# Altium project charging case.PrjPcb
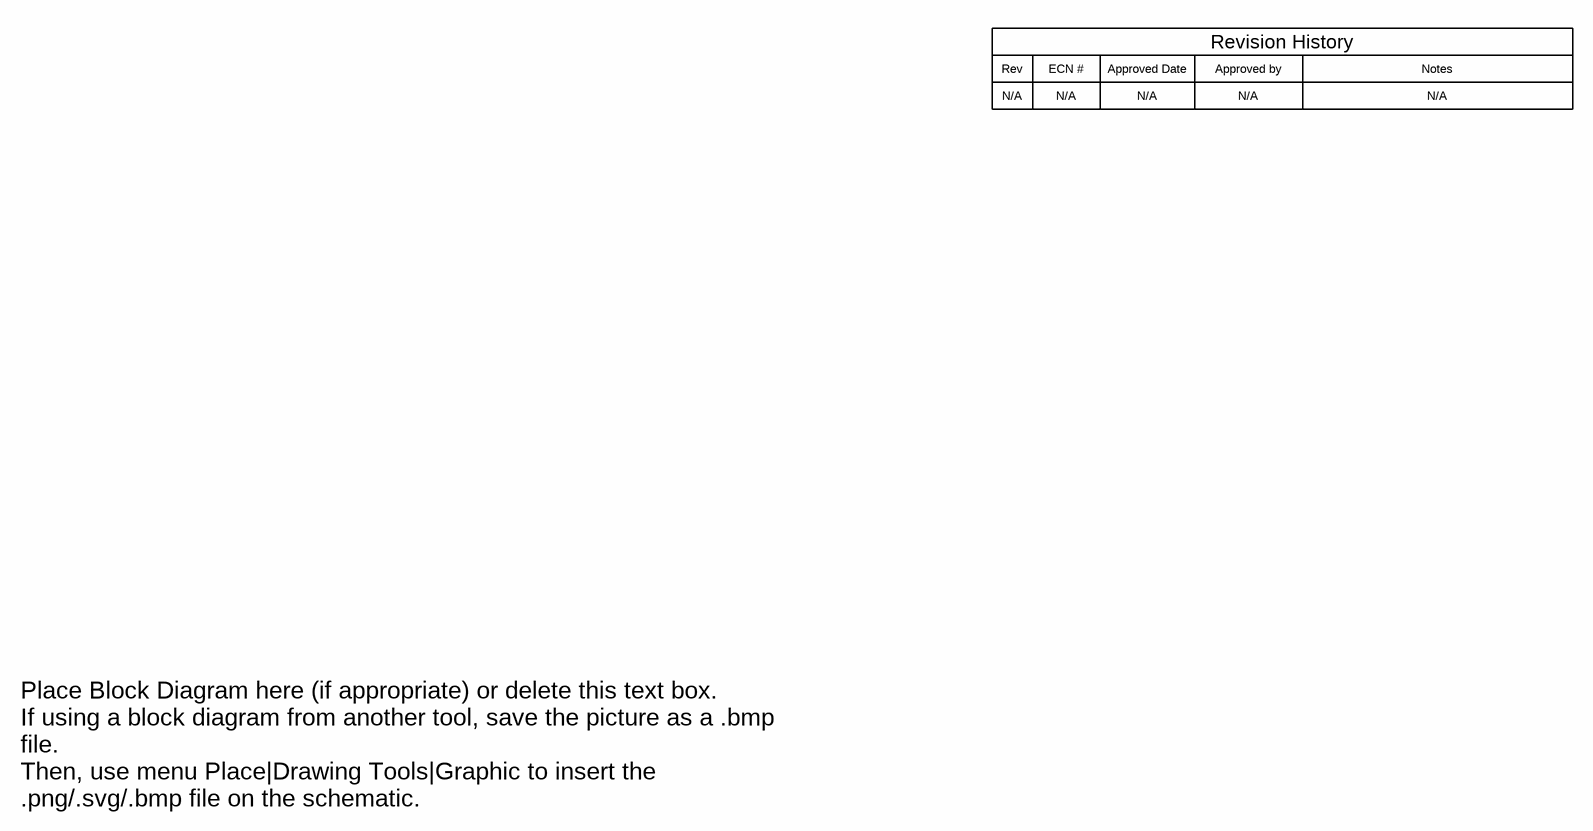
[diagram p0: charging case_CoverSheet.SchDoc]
CopyrightYear: 2017; PCB_Layout: Who did the Layout?; PCB_Rev: E1; PRJ_Customer: Public Release; PRJ_Engineer: Enter name of project lead; PRJ_Number: XX####; PRJ_Title: Change in menu Project|Project Options|Parameters; SCH_Rev: E1; TechSupport: http://www.ti.com/support; TID: N/A
3 sheets, 81 parts. Net scope: global (net labels, ports and power ports of the same name join across sheets).
Board file: charging case_PCB.PcbDoc
Sheets:
  charging case_CoverSheet.SchDoc
  charging case_BlankSheet.SchDoc
  charging case_EVM_Hardware.SchDoc

## Sheet charging case_CoverSheet.SchDoc
size 431 x 279 mm; Date: Not shown in title block; ApprovedBy: Not shown in title block; CheckedBy: Not shown in title block; Author: Not shown in title block; CompanyName: Not shown in title block; Engineer: Not shown in title block; Organization: Not shown in title block; Address1: Not shown in title block; Address2: Not shown in title block; Address3: Not shown in title block; Address4: Not shown in title block; DocumentNumber: 1; Revision: Use project parameter SCH_Rev; SheetNumber: 1; SheetTotal: 3; PageSetup: Record=PageOptions¦CenterHorizontal=True¦CenterVertical=True¦PrintScale=1.00¦XCorrection=1.00¦YCorrection=1.00¦PrintKind=0¦BorderSize=5000000¦LeftOffset=0¦BottomOffset=0¦Orientation=2¦PaperLength=1000¦PaperWidth=1000¦Scale=100¦PaperSource=15¦PrintQuality=600¦MediaType=1¦DitherType=10¦PaperKind=Letter¦PrintScaleMode=1

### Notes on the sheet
- Rev
- N/A
- ECN #
- Approved Date
- Approved by
- Revision History
- Notes
- Place Block Diagram here (if appropriate) or delete this text box.
  If using a block diagram from another tool, save the picture as a .bmp file.
  Then, use menu Place|Drawing Tools|Graphic to insert the .png/.svg/.bmp file on the schematic.

## Sheet charging case_BlankSheet.SchDoc
size 431 x 279 mm; Date: Not shown in title block; ApprovedBy: Not shown in title block; CheckedBy: Not shown in title block; Author: Not shown in title block; CompanyName: Not shown in title block; Engineer: Not shown in title block; Organization: Not shown in title block; Address1: Not shown in title block; Address2: Not shown in title block; Address3: Not shown in title block; Address4: Not shown in title block; DocumentNumber: 1; Revision: Use project parameter SCH_Rev; SheetNumber: 2; SheetTotal: 3; PageSetup: Record=PageOptions¦CenterHorizontal=True¦CenterVertical=True¦PrintScale=1.00¦XCorrection=1.00¦YCorrection=1.00¦PrintKind=0¦BorderSize=5000000¦LeftOffset=0¦BottomOffset=0¦Orientation=2¦PaperLength=1000¦PaperWidth=1000¦Scale=100¦PaperSource=15¦PrintQuality=600¦MediaType=1¦DitherType=10¦PaperKind=Letter¦PrintScaleMode=1
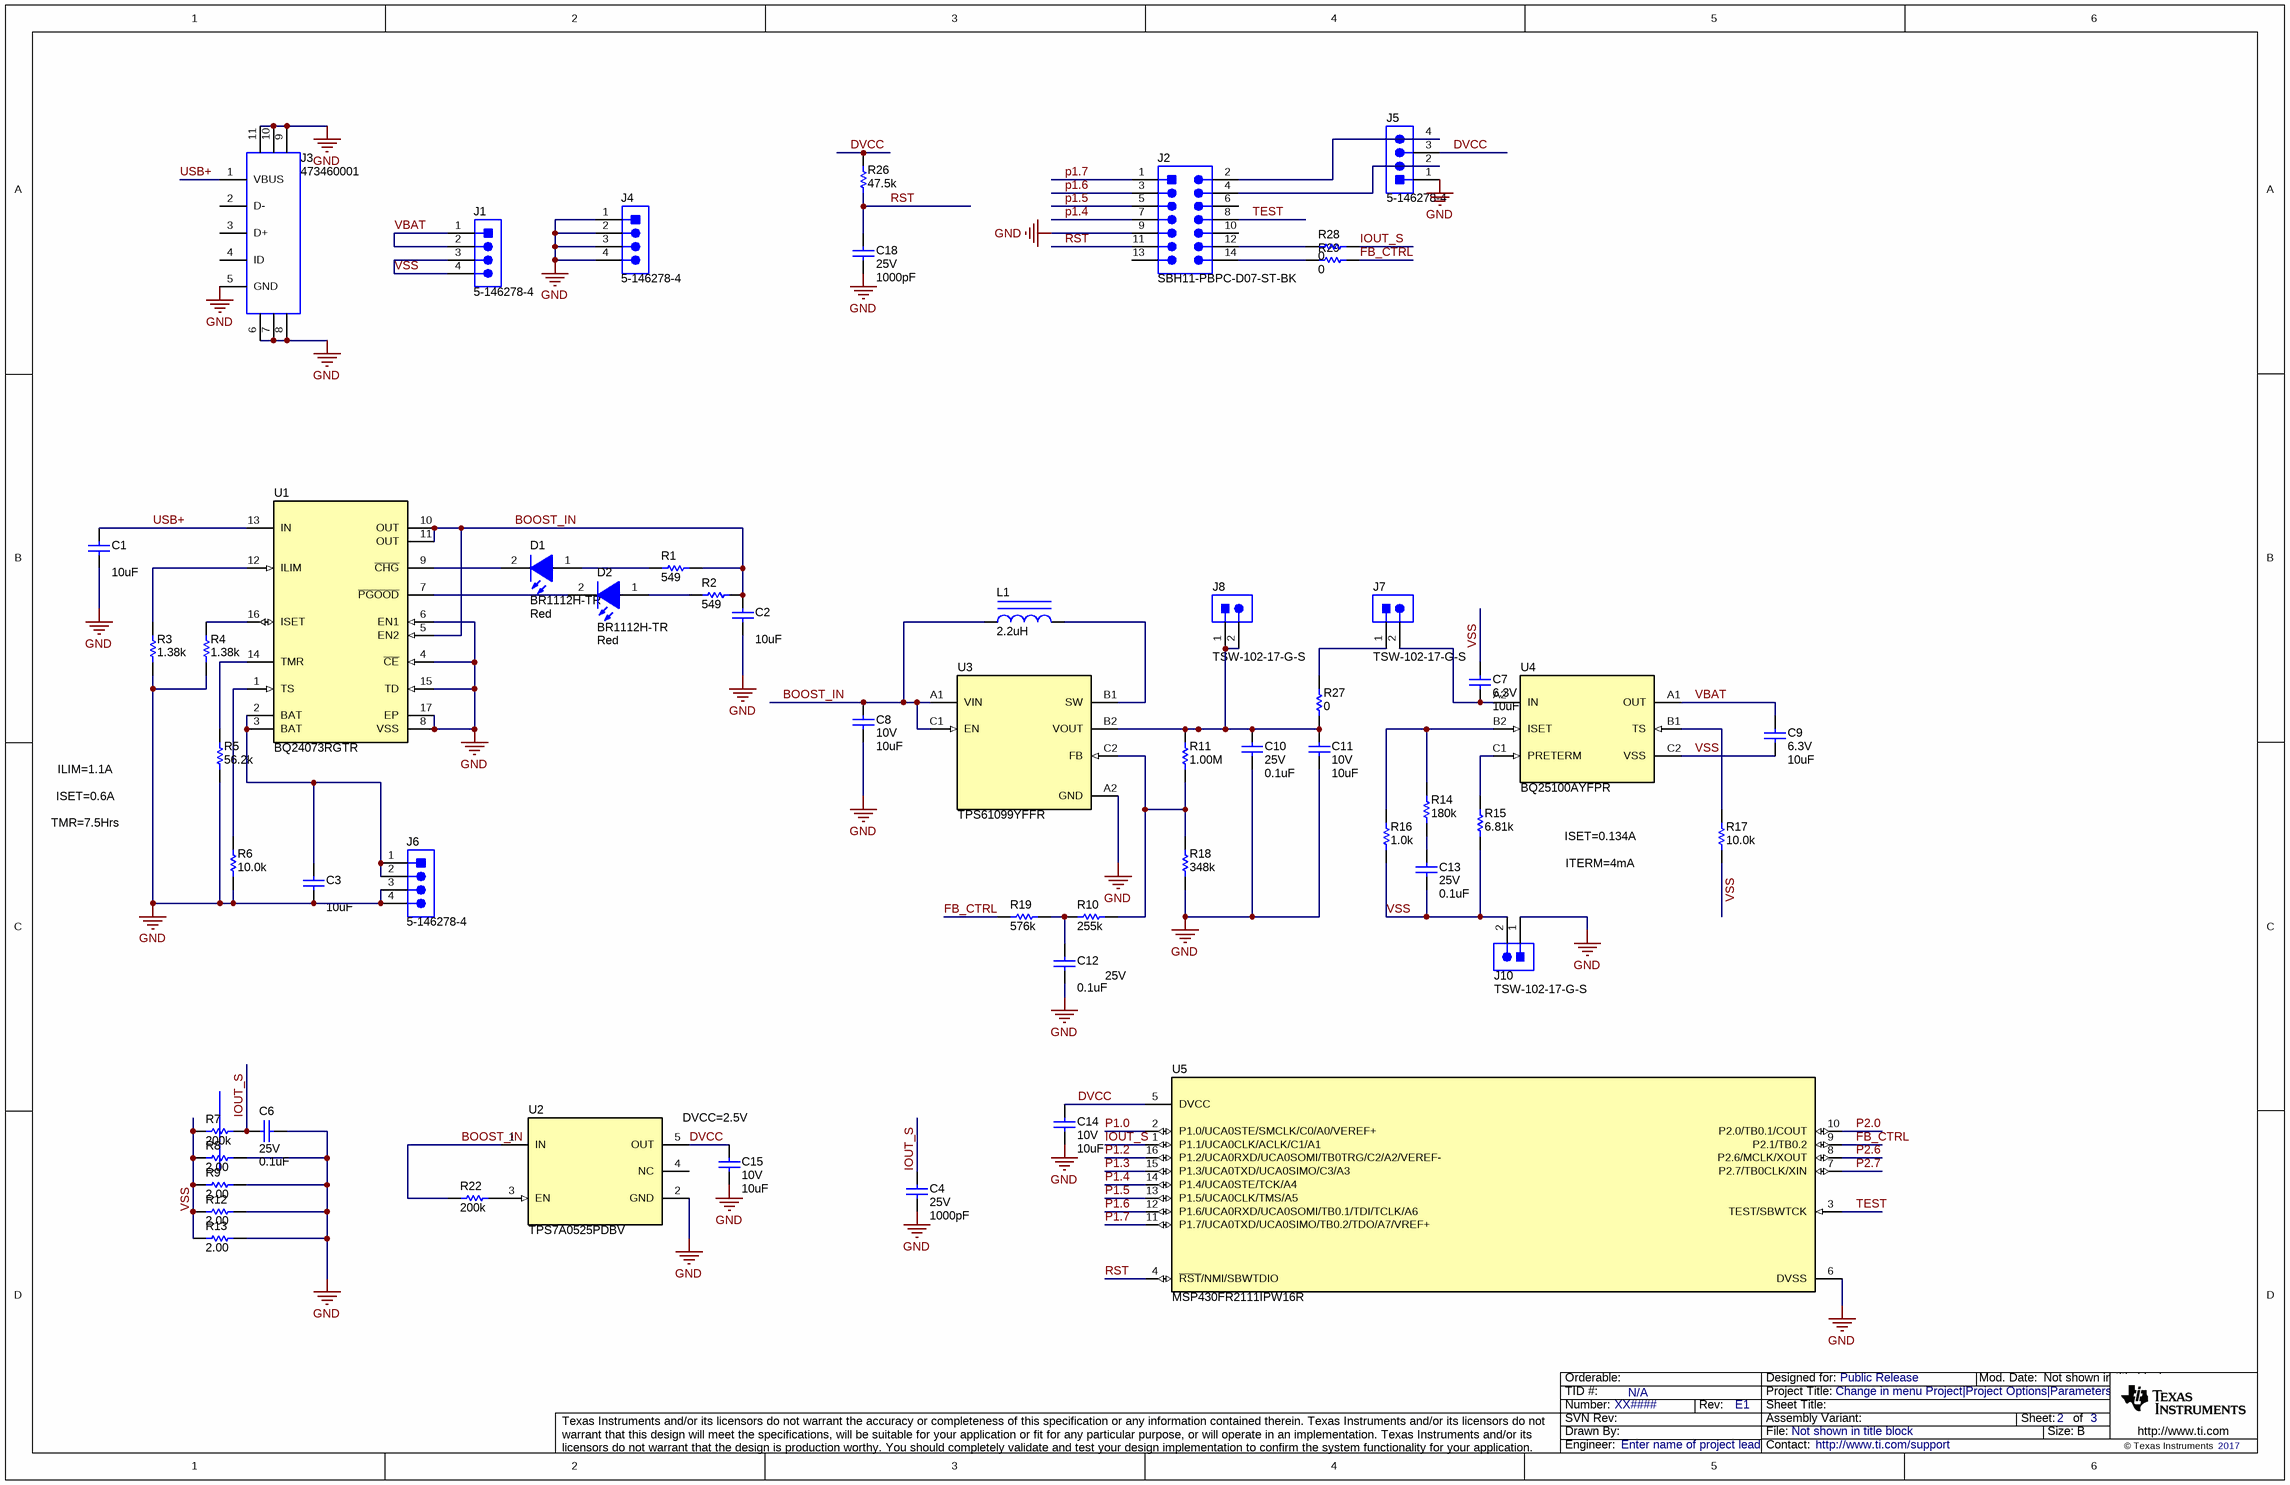
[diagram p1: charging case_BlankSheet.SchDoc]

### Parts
C1  ValueDisplayed: 10uF  [0603]  (hidden comment: GRM188Z71A106MA73D)
C2  ValueDisplayed: 10uF  [0603]  (hidden comment: GRM188Z71A106MA73D)
C3  ValueDisplayed: 10uF  [0603]  (hidden comment: GRM188Z71A106MA73D)
C4  VDC_V: 25V  ValueDisplayed: 1000pF  [0603]  (hidden comment: GRM1885C1E102JA01D)
C6  VDC_V: 25V  ValueDisplayed: 0.1uF  [0603]  (hidden comment: 06033D104KAT2A)
C7  VDC_V: 6.3V  ValueDisplayed: 10uF  [0402_070]  (hidden comment: C1005X5R0J106M050BC)
C8  VDC_V: 10V  ValueDisplayed: 10uF  [0603]  (hidden comment: GRM188Z71A106MA73D)
C9  VDC_V: 6.3V  ValueDisplayed: 10uF  [0402_070]  (hidden comment: C1005X5R0J106M050BC)
C10  VDC_V: 25V  ValueDisplayed: 0.1uF  [0603]  (hidden comment: 06033D104KAT2A)
C11  VDC_V: 10V  ValueDisplayed: 10uF  [0603]  (hidden comment: GRM188Z71A106MA73D)
C12  VDC_V: 25V  ValueDisplayed: 0.1uF  [0603]  (hidden comment: 06033D104KAT2A)
C13  VDC_V: 25V  ValueDisplayed: 0.1uF  [0402]  (hidden comment: GRM155R61E104KA87D)
C14  VDC_V: 10V  ValueDisplayed: 10uF  [0603]  (hidden comment: GRM188Z71A106MA73D)
C15  VDC_V: 10V  ValueDisplayed: 10uF  [0603]  (hidden comment: GRM188Z71A106MA73D)
C18  VDC_V: 25V  ValueDisplayed: 1000pF  [0603]  (hidden comment: GRM1885C1E102JA01D)
D1  BR1112H-TR  value Red  [BR1112H_Red]
D2  BR1112H-TR  value Red  [BR1112H_Red]
J1  5-146278-4  [TE_5-146278-4]
J2  SBH11-PBPC-D07-ST-BK  [CONN_SBH11-PBPC-D07-ST-BK]
J3  473460001  [CONN_47346-0001]
J4  5-146278-4  [TE_5-146278-4]
J5  5-146278-4  [TE_5-146278-4]
J6  5-146278-4  [TE_5-146278-4]
J7  TSW-102-17-G-S  [Samtec_TSW-102-17-x-S]
J8  TSW-102-17-G-S  [Samtec_TSW-102-17-x-S]
J10  TSW-102-17-G-S  [Samtec_TSW-102-17-x-S]
L1  ValueDisplayed: 2.2uH  [DFE252012C]  (hidden comment: DFE252012F-2R2M=P2)
R1  ValueDisplayed: 549  [0603]  (hidden comment: RT0603DRE07549RL)
R2  ValueDisplayed: 549  [0603]  (hidden comment: RT0603DRE07549RL)
R3  ValueDisplayed: 1.38k  [0603]  (hidden comment: RT0603DRE071K38L)
R4  ValueDisplayed: 1.38k  [0603]  (hidden comment: RT0603DRE071K38L)
R5  ValueDisplayed: 56.2k  [0603]  (hidden comment: RC0603FR-0756K2L)
R6  ValueDisplayed: 10.0k  [0603]  (hidden comment: RC0603FR-0710KL)
R7  ValueDisplayed: 200k  [0603]  (hidden comment: RG1608P-204-B-T5)
R8  ValueDisplayed: 2.00  [0603]  (hidden comment: RC0603FR-072RL)
R9  ValueDisplayed: 2.00  [0603]  (hidden comment: RC0603FR-072RL)
R10  ValueDisplayed: 255k  [0603]  (hidden comment: RT0603DRE07255KL)
R11  ValueDisplayed: 1.00M  [0603]  (hidden comment: MCT06030C1004FP500)
R12  ValueDisplayed: 2.00  [0603]  (hidden comment: RC0603FR-072RL)
R13  ValueDisplayed: 2.00  [0603]  (hidden comment: RC0603FR-072RL)
R14  ValueDisplayed: 180k  [0402]  (hidden comment: RC0402FR-07180KL)
R15  ValueDisplayed: 6.81k  [0402]  (hidden comment: RC0402FR-076K81L)
R16  ValueDisplayed: 1.0k  [0603]  (hidden comment: RC0603JR-071KL)
R17  ValueDisplayed: 10.0k  [0402]  (hidden comment: RC0402FR-0710KL)
R18  ValueDisplayed: 348k  [0603]  (hidden comment: RT0603DRE07348KL)
R19  ValueDisplayed: 576k  [0603]  (hidden comment: RC0603FR-07576KL)
R22  ValueDisplayed: 200k  [0603]  (hidden comment: RG1608P-204-B-T5)
R26  ValueDisplayed: 47.5k  [0603]  (hidden comment: RT0603BRD0747K5L)
R27  ValueDisplayed: 0  [0603]  (hidden comment: RMCF0603ZT0R00)
R28  ValueDisplayed: 0  [0603]  (hidden comment: RMCF0603ZT0R00)
R29  ValueDisplayed: 0  [0603]  (hidden comment: RMCF0603ZT0R00)
U1  PartNumber: BQ24073RGTR  [RGT0016C]  (hidden comment: BQ24230RGTR)
U2  PartNumber: TPS7A0525PDBV  [DBV0005A_N]  (hidden comment: TPS7A0533PDBV)
U3  TPS61099YFFR  [YFF0006AFAD]
U4  BQ25100AYFPR  [YFP0006AFAV]
U5  MSP430FR2111IPW16R  [PW0016A_L]

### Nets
GND: C1.2 C2.2 C3.2 C4.2 C6.1 C8.2 C10.2 C11.2 C12.2 C14.2 C15.2 C18.2 J2.9 J3.5(GND) J3.6 J3.7 J3.8 J3.9 J3.10 J3.11 J4.1 J4.2 J4.3 J4.4 J5.1 J6.3 J6.4 J10.1 R3.1 R4.1 R5.1 R6.1 R8.2 R9.2 R12.2 R13.2 R18.1 U1.4(~{CE}) U1.6(EN1) U1.8(VSS) U1.15(TD) U1.17(EP) U2.2(GND) U3.A2(GND) U5.6(DVSS)
BOOST_IN: C2.1 C8.1 L1.1 R1.1 R2.1 R22.2 U1.5(EN2) U1.10(OUT) U1.11(OUT) U2.1(IN) U3.A1(VIN) U3.C1(EN)
DVCC: C14.1 C15.1 J5.3 R26.2 U2.5(OUT) U5.5(DVCC)
FB_CTRL: R19.1 R29.1 U5.9(P2.1/TB0.2)
IOUT_S: C4.1 C6.2 R7.1 R28.1 U5.1(P1.1/UCA0CLK/ACLK/C1/A1)
P1.0: U5.2(P1.0/UCA0STE/SMCLK/C0/A0/VEREF+)
P1.2: U5.16(P1.2/UCA0RXD/UCA0SOMI/TB0TRG/C2/A2/VEREF-)
P1.3: U5.15(P1.3/UCA0TXD/UCA0SIMO/C3/A3)
P1.4: J2.7 U5.14(P1.4/UCA0STE/TCK/A4)
P1.5: J2.5 U5.13(P1.5/UCA0CLK/TMS/A5)
P1.6: J2.3 U5.12(P1.6/UCA0RXD/UCA0SOMI/TB0.1/TDI/TCLK/A6)
P1.7: J2.1 U5.11(P1.7/UCA0TXD/UCA0SIMO/TB0.2/TDO/A7/VREF+)
P2.0: U5.10(P2.0/TB0.1/COUT)
P2.6: U5.8(P2.6/MCLK/XOUT)
P2.7: U5.7(P2.7/TB0CLK/XIN)
RST: C18.1 J2.11 R26.1 U5.4(~{RST}/NMI/SBWTDIO)
TEST: J2.8 U5.3(TEST/SBWTCK)
USB+: C1.1 J3.1(VBUS) U1.13(IN)
VBAT: C9.1 J1.1 J1.2 U4.A1(OUT)
VSS: C7.1 C9.2 C13.2 J1.3 J1.4 J10.2 R7.2 R8.1 R9.1 R12.1 R13.1 R15.1 R16.1 R17.1 U4.C2(VSS)
NetC3_1: C3.1 J6.1 J6.2 U1.2(BAT) U1.3(BAT)
NetC7_2: C7.2 J7.2 U4.A2(IN)
NetC10_1: C10.1 C11.1 J8.1 J8.2 R11.2 R27.1 U3.B2(VOUT)
NetC12_1: C12.1 R10.1 R19.2
NetC13_1: C13.1 R14.1
NetD1_1: D1.1(A) R1.2
NetD1_2: D1.2(K) U1.9(~{CHG})
NetD2_1: D2.1(A) R2.2
NetD2_2: D2.2(K) U1.7(~{PGOOD})
NetJ2_2: J2.2 J5.4
NetJ2_4: J2.4 J5.2
NetJ2_12: J2.12 R28.2
NetJ2_14: J2.14 R29.2
NetJ7_1: J7.1 R27.2
NetL1_2: L1.2 U3.B1(SW)
NetR3_2: R3.2 U1.12(ILIM)
NetR4_2: R4.2 U1.16(ISET)
NetR5_2: R5.2 U1.14(TMR)
NetR6_2: R6.2 U1.1(TS)
NetR10_2: R10.2 R11.1 R18.2 U3.C2(FB)
NetR14_2: R14.2 R16.2 U4.B2(ISET)
NetR15_2: R15.2 U4.C1(PRETERM)
NetR17_2: R17.2 U4.B1(TS)
NetR22_1: R22.1 U2.3(EN)

Not connected (* = marked no-connect by the designer): J2 6 10 13; J3 2(D-) 3(D+) 4(ID); U2 4(NC)

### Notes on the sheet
- ILIM=1.1A
- ISET=0.6A
- TMR=7.5Hrs
- ISET=0.134A
- ITERM=4mA
- DVCC=2.5V

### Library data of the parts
C1 = CMP-0007497-5: CAP, CERM, 10 uF, 10 V, +/- 20%, X7R, 0603; Manufacturer: MuRata; TaMin_C: -55°C; Polarized: N; SizeAreaWB_mm2: 4.68; Value1: Unknown; U/M: EA; Value: 10uF; TaMax_C: 125°C; SizeZ_mm: 1; SizeX_mm: 1.6; SizeY_mm: 0.8; Value2: 10V; SizeArea_mm2: 1.28; Cap_F: 10µF; AEC Category: Q200
C2 C3 = CMP-0007497-5: CAP, CERM, 10 uF, 10 V, +/- 20%, X7R, 0603; Manufacturer: MuRata; TaMin_C: -55°C; Polarized: N; SizeAreaWB_mm2: 4.68; Value1: Unknown; U/M: EA; Value: 10uF; TaMax_C: 125°C; SizeZ_mm: 1; SizeX_mm: 1.6; SizeY_mm: 0.8; Value2: 10V; SizeArea_mm2: 1.28; CompType: Capacitor; Cap_F: 10µF; AEC Category: Q200
C4 C18 = CMP-0007159-4: CAP, CERM, 1000 pF, 25 V, +/- 5%, C0G/NP0, 0603; Manufacturer: MuRata; TaMin_C: -55°C; Polarized: N; SizeAreaWB_mm2: 4.68; Value1: Unknown; U/M: EA; Value: 1000pF; TaMax_C: 125°C; SizeZ_mm: 1; SizeX_mm: 1.6; SizeY_mm: 0.8; SizeArea_mm2: 1.28; Cap_F: 1nF; AEC Category: Q200
C6 C10 C12 = CMP-0006758-5: CAP, CERM, 0.1 uF, 25 V, +/- 10%, X5R, 0603; Manufacturer: AVX; TaMin_C: -55°C; ESR_ohm: 0.048; Polarized: N; SizeAreaWB_mm2: 4.68; Value1: 0.048 ohm; U/M: EA; Value: 0.1uF; TaMax_C: 85°C; SizeZ_mm: 1; SizeX_mm: 1.6; SizeY_mm: 0.8; SizeArea_mm2: 1.28; Cap_F: 100nF; IRMS_A: 5.3dA; AEC Category: Q200
C7 = CMP-0006257-2: CAP, CERM, 10 uF, 6.3 V, +/- 20%, X5R, 0402; Manufacturer: TDK; TaMin_C: -55°C; ESR_ohm: 3.019m; Polarized: N; SizeAreaWB_mm2: 3; Value1: 0.003019 ohm; U/M: EA; Value: 10uF; TaMax_C: 85°C; SizeZ_mm: 0.7; SizeX_mm: 1; SizeY_mm: 0.5; Cap_F: 10µF; IRMS_A: 2.87803A; AEC Category: Q200
C8 C11 C14 C15 = CMP-0007497-5: CAP, CERM, 10 uF, 10 V, +/- 20%, X7R, 0603; Manufacturer: MuRata; TaMin_C: -55°C; Polarized: N; SizeAreaWB_mm2: 4.68; Value1: Unknown; U/M: EA; Value: 10uF; TaMax_C: 125°C; SizeZ_mm: 1; SizeX_mm: 1.6; SizeY_mm: 0.8; SizeArea_mm2: 1.28; Cap_F: 10µF; AEC Category: Q200
C9 = CMP-0006257-2: CAP, CERM, 10 uF, 6.3 V, +/- 20%, X5R, 0402; Manufacturer: TDK; TaMin_C: -55°C; ESR_ohm: 3.019m; Polarized: N; SizeAreaWB_mm2: 3; Value1: 0.003019 ohm; U/M: EA; Value: 10uF; TaMax_C: 85°C; SizeZ_mm: 0.7; SizeX_mm: 1; SizeY_mm: 0.5; CompType: Capacitor; Cap_F: 10µF; IRMS_A: 2.87803A; AEC Category: Q200
C13 = CMP-0006607-2: CAP, CERM, 0.1 uF, 25 V, +/- 10%, X5R, 0402; Manufacturer: MuRata; TaMin_C: -55°C; Polarized: N; SizeAreaWB_mm2: 3; Value1: Unknown; U/M: EA; Value: 0.1uF; TaMax_C: 85°C; SizeZ_mm: 0.6; SizeX_mm: 1; SizeY_mm: 0.5; CompType: Capacitor; Cap_F: 100nF; AEC Category: Q200
D1 D2 = CMP-0067678-1: LED, Red, SMD; Manufacturer: Stanley Electric Co., LTD; Io_A: 20mA; Power_TotalModule: 57.5mW; Green_Lifecycle: Not Set; SizeAreaWB_mm2: 6.75; Vr_V: 4V; Tjmax_C: 85°C; Green_REACh: Incomplete; Value1: 0.0575W; U/M: EA; Angle: 150.0; SizeZ_mm: 0.9; SizeX_mm: 2.0; SizeY_mm: 1.25; Ir_A: 100µA; Vf_V: 1.7V; SizeArea_mm2: 2.5
J1 J4-J6 = CMP-0054950-1: Header, 100mil, 4x1, Tin, TH; Manufacturer: TE Connectivity; CNHeader: TRUE; Green_Lifecycle: Active; Green_REACh: Passed; CT: FALSE
J2 = CMP-0054695-1: Header (shrouded), 100 mil, 7x2, Gold, TH; Manufacturer: Sullins Connector Solutions; CT: FALSE; Green_REACh: Incomplete; Green_Lifecycle: Not Set
J3 = CMP-0055296-1: Connector, Receptacle, Micro-USB Type B, R/A, Bottom Mount SMT; Manufacturer: Molex; CNHeader: FALSE; Green_Lifecycle: Active; Gender: Female; Green_REACh: Passed; CompType: USB; CT: TRUE
J7 J8 J10 = CMP-0077742-1: Header, 2.54mm, 2x1, Gold, TH; Manufacturer: Samtec; Pitch_mm: 2.54; Gender: Male; Cert_CSA: Y; Shrouded: N; Row_Count: 1
L1 = CMP-0058932-1: Inductor, Shielded, Powdered Iron, 2.2 uH, 2.3 A, 0.082 ohm, SMD; Manufacturer: MuRata Toko; Isat: 3.3A @ 30% inductance drop; Irms: 2.3A @ 40C rise; SizeAreaWB_mm2: 11.84; DCR_ohm: 0.082; Value: 2.2uH; Imax_A: 2.3A; SizeZ_mm: 1.2; SizeX_mm: 2.7; SizeY_mm: 2.2; SizeArea_mm2: 5.94; Ind_H: 2.2µH; AEC Qualified: N; AEC Category: Q200
R1 = CMP-0025400-3: RES, 549, 0.5%, 0.1 W, 0603; Manufacturer: Yageo America; Power_W: 100mW; TempCo: 50 ppm/C; Value_Code: 549R; U/M: EA; Value: 549; EIA_Code: E192; SizeX_mm: 1.6; SizeY_mm: 0.8; SizeZ_mm: 1; Value2: 0.1W; SizeArea_mm2: 1.28; CompType: Resistor; VDC_V: 75V; AEC Category: Q200
R2 = CMP-0025400-3: RES, 549, 0.5%, 0.1 W, 0603; Manufacturer: Yageo America; Power_W: 100mW; TempCo: 50 ppm/C; Value_Code: 549R; U/M: EA; Value: 549; EIA_Code: E192; SizeX_mm: 1.6; SizeY_mm: 0.8; SizeZ_mm: 1; Value2: 0.1W; SizeArea_mm2: 1.28; VDC_V: 75V; AEC Category: Q200
R3 R4 = CMP-0024820-3: RES, 1.38 k, 0.5%, 0.1 W, 0603; Manufacturer: Yageo America; Power_W: 100mW; TempCo: 50 ppm/C; Value_Code: 1k38; U/M: EA; Value: 1.38k; EIA_Code: E192; SizeX_mm: 1.6; SizeY_mm: 0.8; SizeZ_mm: 1; Value2: 0.1W; SizeArea_mm2: 1.28; VDC_V: 75V; AEC Category: Q200
R5 = CMP-0023186-3: RES, 56.2 k, 1%, 0.1 W, 0603; Manufacturer: Yageo America; Power_W: 100mW; TempCo: 200 ppm/C; Value_Code: 56k2; U/M: EA; Value: 56.2k; EIA_Code: E96; SizeX_mm: 1.6; SizeY_mm: 0.8; SizeZ_mm: 1; Value2: 0.1W; SizeArea_mm2: 1.28; VDC_V: 150V; AEC Category: Q200
R6 = CMP-0022746-3: RES, 10.0 k, 1%, 0.1 W, 0603; Manufacturer: Yageo America; Power_W: 100mW; TempCo: 200 ppm/C; Value_Code: 10k0; U/M: EA; Value: 10.0k; EIA_Code: E96; Res_ohm: 10k; SizeX_mm: 1.6; SizeY_mm: 0.8; SizeZ_mm: 1; Value2: 0.1W; SizeArea_mm2: 1.28; CompType: Resistor; VDC_V: 150V; AEC Category: Q200
R7 R22 = CMP-0023465-3: RES, 200 k, 0.1%, 0.1 W, 0603; Manufacturer: Susumu Co Ltd; Power_W: 100mW; TempCo: 25 ppm/C; U/M: EA; Value: 200k; EIA_Code: E192; SizeX_mm: 1.6; SizeY_mm: 0.8; SizeZ_mm: 1; Value2: 0.1W; SizeArea_mm2: 1.28; CompType: Resistor; VDC_V: 75V; AEC Category: Q200
R8 R9 R12 R13 = CMP-0023011-4: RES, 2.00, 1%, 0.1 W, 0603; Manufacturer: Yageo; Power_W: 100mW; TempCo: 200 ppm/C; Value_Code: 2R00; Value: 2.00; EIA_Code: E96; Res_ohm: 2; SizeX_mm: 1.6; SizeY_mm: 0.8; SizeZ_mm: 1; Value2: 0.1W; SizeArea_mm2: 1.28; AEC Qualified: N; VDC_V: 75V; AEC Category: Q200; SizeAreaWB_mm2: 4.68
R10 = CMP-0024989-3: RES, 255 k, 0.5%, 0.1 W, 0603; Manufacturer: Yageo America; Power_W: 100mW; TempCo: 50 ppm/C; U/M: EA; Value: 255k; EIA_Code: E192; SizeX_mm: 1.6; SizeY_mm: 0.8; SizeZ_mm: 1; Value2: 0.1W; SizeArea_mm2: 1.28; VDC_V: 75V; AEC Category: Q200
R11 = CMP-0022731-2: RES, 1.00 M, 1%, 0.125 W, 0603; Manufacturer: Vishay/Beyschlag; Power_W: 125mW; TempCo: 50 ppm/C; Value_Code: 1M00; U/M: EA; Value: 1.00Meg; EIA_Code: E96; Res_ohm: 1M; SizeX_mm: 1.6; SizeY_mm: 0.8; SizeZ_mm: 1; Value2: 0.125W; SizeArea_mm2: 1.28; CompType: Resistor; AEC Qualified: N; VDC_V: 75V; AEC Category: Q200
R14 = CMP-0026723-1: RES, 180 k, 1%, 0.063 W, 0402; Manufacturer: Yageo America; Power_W: 63mW; TempCo: 100 ppm/C; U/M: EA; Value: 180k; SizeX_mm: 1; SizeY_mm: 0.5; SizeZ_mm: 0.6; Value2: 0.063W; AEC Qualified: N; VDC_V: 50V; AEC Category: Q200
R15 = CMP-0078787-1: RES, 6.81 k, 1%, 0.063 W, 0402; Manufacturer: Yageo America; Value_Code: 6k81; SizeArea_mm2: 0.5; AEC Qualified: N; AEC Category: Q200; Value: 6.81k; SizeZ_mm: 0.6; EIA_Code: E96; TempCo: 100 ppm/C; Power_W: 63mW; VDC_V: 50V; Value2: 0.063W; SizeX_mm: 1
R16 = CMP-0025899-5: RES, 1.0 k, 5%, 0.1 W, 0603; Manufacturer: Yageo; Power_W: 100mW; TempCo: 100 ppm/C; Value_Code: 1k00; Value: 1.0k; EIA_Code: E24; Res_ohm: 1k; SizeX_mm: 1.6; SizeY_mm: 0.8; SizeZ_mm: 1; Value2: 0.1W; SizeArea_mm2: 1.28; AEC Qualified: N; VDC_V: 75V; AEC Category: Q200; SizeAreaWB_mm2: 4.68
R17 = CMP-0078669-1: RES, 10.0 k, 1%, 0.063 W, 0402; Manufacturer: Yageo America; Power_W: 63mW; Green_Lifecycle: Active; TempCo: 100 ppm/C; Value_Code: 10k0; Green_REACh: Passed; Value: 10.0k; EIA_Code: E96; Res_ohm: 10k; SizeX_mm: 1; SizeY_mm: 0.5; SizeZ_mm: 0.6; Value2: 0.063W; AEC Qualified: N; AEC Category: Q200
R18 = CMP-0025159-3: RES, 348 k, 0.5%, 0.1 W, 0603; Manufacturer: Yageo America; Power_W: 100mW; TempCo: 50 ppm/C; U/M: EA; Value: 348k; EIA_Code: E192; SizeX_mm: 1.6; SizeY_mm: 0.8; SizeZ_mm: 1; Value2: 0.1W; SizeArea_mm2: 1.28; VDC_V: 75V; AEC Category: Q200
R19 = CMP-0023189-2: RES, 576 k, 1%, 0.1 W, 0603; Manufacturer: Yageo America; Power_W: 100mW; TempCo: 200 ppm/C; U/M: EA; Value: 576k; EIA_Code: E96; SizeX_mm: 1.6; SizeY_mm: 0.8; SizeZ_mm: 1; Value2: 0.1W; SizeArea_mm2: 1.28; VDC_V: 150V; AEC Category: Q200
R26 = CMP-0024266-3: RES, 47.5 k, 0.1%, 0.1 W, 0603; Manufacturer: Yageo America; Power_W: 100mW; TempCo: 25 ppm/C; Value_Code: 47k5; U/M: EA; Value: 47.5k; EIA_Code: E192; SizeX_mm: 1.6; SizeY_mm: 0.8; SizeZ_mm: 1; Value2: 0.1W; SizeArea_mm2: 1.28; VDC_V: 75V; AEC Category: Q200
R27-R29 = CMP-0023343-3: RES, 0, 1%, 0.1 W, AEC-Q200 Grade 0, 0603; Manufacturer: Stackpole Electronics Inc; Power_W: 100mW; TempCo: ppm/C; U/M: EA; Value: 0; SizeX_mm: 1.6; SizeY_mm: 0.8; SizeZ_mm: 1; Value2: 0.1W; SizeArea_mm2: 1.28; AEC Qualified: Y; AEC Category: Q200
U1 = CMP-0034120-2: USB Friendly 0.5 A Li+ Charger with Dynamic Power Management, 6.6 V OVP, 4.3 V, -40 to 85 degC, 16-pin QFN (RGT), Green (RoHS & no Sb/Br); Manufacturer: Texas Instruments; SubFamily: Battery Charge Management; Vin(Min)(V): 4.3; NiCd: N
U2 = CMP-0013051-2: 1uA IQ, 200 mA, Ultralow IQ Low-Dropout Regulator, DBV0005A (SOT-5); Manufacturer: Texas Instruments; SizeX_mm: 2.8; SizeY_mm: 2.9; CompType: IC; SizeZ_mm: 1.45; SizeArea_mm2: 8.12; SizeAreaWB_mm2: 14.82; U/M: EA
U3 = CMP-0074075-1: Synchronous Boost Converter with 800 nA Ultra-Low Quiescent Current, YFF0006AFAD (DSBGA-6); Alternate PartNumber: TPS61099YFFT; Alternate Manufacturer: Texas Instruments; SizeAreaWB_mm2: 4.193784; U/M: EA; SizeZ_mm: 0.625; SizeX_mm: 0.884; SizeY_mm: 1.226; SizeArea_mm2: 1.083784; CompType: IC
U4 = CMP-0076143-1: 250-mA Single Cell Li-Ion Battery Charger, 1mA termination, 75nA Battery leakage, YFP0006AFAV (DSBGA-6); Manufacturer: Texas Instruments; Alternate PartNumber: BQ25100AYFPT; SizeAreaWB_mm2: 4.84664; SizeArea_mm2: 1.38864; SizeZ_mm: 0.5; SizeY_mm: 1.578; U/M: EA; CompType: IC; SizeX_mm: 0.88
U5 = CMP-0076600-1: 16 MHz Ultra-Low-Power Microcontroller With 4 KB FRAM, 1 KB SRAM, 12 IO, 8 ch ADC10, PW0016A (TSSOP-16); Manufacturer: Texas Instruments; SizeAreaWB_mm2: 58.8; SizeArea_mm2: 32.0; SizeZ_mm: 1.2; SizeY_mm: 5.0; U/M: EA; CompType: IC; SizeX_mm: 6.4

## Sheet charging case_EVM_Hardware.SchDoc
size 431 x 279 mm; Date: Not shown in title block; ApprovedBy: Not shown in title block; CheckedBy: Not shown in title block; Author: Not shown in title block; CompanyName: Not shown in title block; Engineer: Not shown in title block; Organization: Not shown in title block; Address1: Not shown in title block; Address2: Not shown in title block; Address3: Not shown in title block; Address4: Not shown in title block; DocumentNumber: 1; Revision: Use project parameter SCH_Rev; SheetNumber: 3; SheetTotal: 3; PageSetup: Record=PageOptions¦CenterHorizontal=True¦CenterVertical=True¦PrintScale=1.00¦XCorrection=1.00¦YCorrection=1.00¦PrintKind=0¦BorderSize=5000000¦LeftOffset=0¦BottomOffset=0¦Orientation=2¦PaperLength=1000¦PaperWidth=1000¦Scale=100¦PaperSource=15¦PrintQuality=600¦MediaType=1¦DitherType=10¦PaperKind=Letter¦PrintScaleMode=1
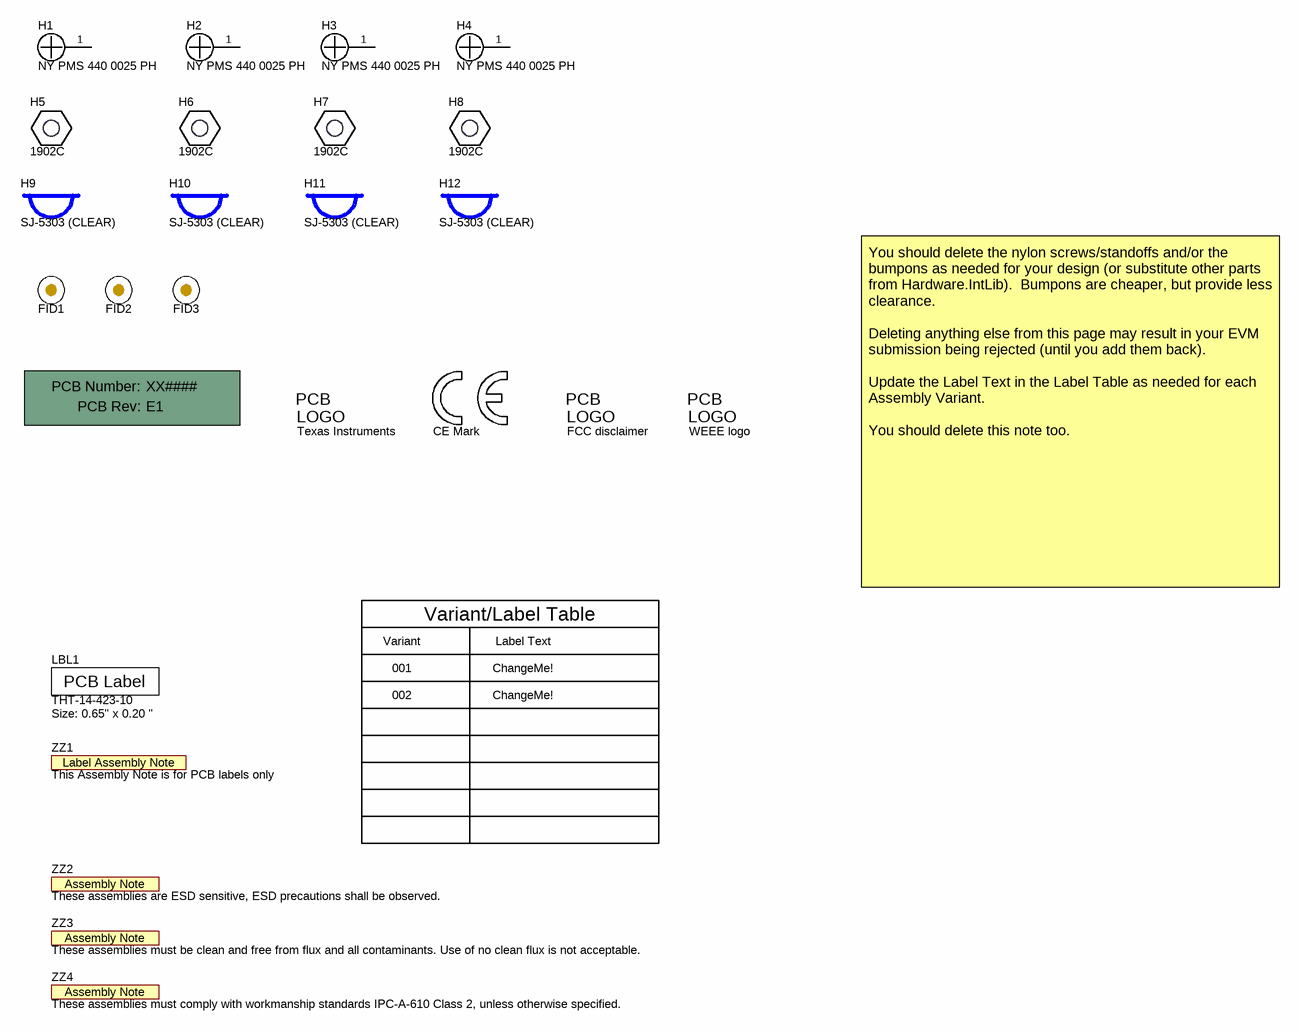
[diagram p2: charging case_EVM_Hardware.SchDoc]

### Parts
!PCB  Printed Circuit Board  (value not drawn)  (mechanical)
FID1  Fiducial  [Fiducial10-20]  (value not drawn)
FID2  Fiducial  [Fiducial10-20]  (value not drawn)
FID3  Fiducial  [Fiducial10-20]  (value not drawn)
H1  NY PMS 440 0025 PH  [NY PMS 440 0025 PH]
H2  NY PMS 440 0025 PH  [NY PMS 440 0025 PH]
H3  NY PMS 440 0025 PH  [NY PMS 440 0025 PH]
H4  NY PMS 440 0025 PH  [NY PMS 440 0025 PH]
H5  1902C  [Keystone_1902C]
H6  1902C  [Keystone_1902C]
H7  1902C  [Keystone_1902C]
H8  1902C  [Keystone_1902C]
H9  SJ-5303 (CLEAR)  [Bumpon_SJ5003Transparent]
H10  SJ-5303 (CLEAR)  [Bumpon_SJ5003Transparent]
H11  SJ-5303 (CLEAR)  [Bumpon_SJ5003Transparent]
H12  SJ-5303 (CLEAR)  [Bumpon_SJ5003Transparent]
LBL1  THT-14-423-10  Note: Size: 0.65" x 0.20 "  [Label_650x200]
Logo1  Texas Instruments  [TI_Stacked_Overlay_Small]  (no BOM)
Logo2  CE Mark  [CE_Mark_5mm]  (no BOM)
Logo3  FCC disclaimer  [FCC_disclaimer]  (no BOM)
Logo4  WEEE logo  [WEEE_Minimum]  (no BOM)
ZZ1  This Assembly Note is for PCB labels only  [AssemblyNoteLabel]  (no BOM)
ZZ2  These assemblies are ESD sensitive, ESD precautions shall be observed.  [AssemblyNote]  (no BOM)
ZZ3  These assemblies must be clean and free from flux and all contaminants. Use of no clean flux is not acceptable.  [AssemblyNote]  (no BOM)
ZZ4  These assemblies must comply with workmanship standards IPC-A-610 Class 2, unless otherwise specified.  [AssemblyNote]  (no BOM)

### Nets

Not connected (* = marked no-connect by the designer): H1 1; H2 1; H3 1; H4 1

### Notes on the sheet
- Variant
- Variant/Label Table
- Label Text
- You should delete the nylon screws/standoffs and/or the bumpons as needed for your design (or substitute other parts from Hardware.IntLib).  Bumpons are cheaper, but provide less clearance.
  Deleting anything else from this page may result in your EVM submission being rejected (until you add them back).
  Update the Label Text in the Label Table as needed for each Assembly Variant.
  You should delete this note too.
- 001
- 002
- ChangeMe!

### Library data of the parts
!PCB = CMP-0003618-2: Manufacturer: Any; PartNumber: XX####
FID1-FID3 = CMP-0077181-1: Fiducial mark.  There is nothing to buy or mount.
H1-H4 = CMP-0003617-1: Machine Screw, Round, #4-40 x 1/4, Nylon, Philips panhead; Manufacturer: B&F Fastener Supply; CompType: Hardware
H5-H8 = CMP-0003610-1: Standoff, Hex, 0.5"L #4-40 Nylon; Manufacturer: Keystone; CompType: Hardware
H9-H12 = CMP-0003620-1: Bumpon, Hemisphere, 0.44 X 0.20, Clear; Manufacturer: 3M
LBL1 = CMP-0003625-1: Thermal Transfer Printable Labels, 0.650" W x 0.200" H - 10,000 per roll; Manufacturer: Brady; CompType: Label
Logo1 = CMP-0074838-1: Texas Instrument Corporate Signature; SymbolCreator: a0412235; Lib Reference: TI_Logo; Library Reference: Logo
Logo2 = CMP-0074844-1: SymbolCreator: a0412235
Logo3 = CMP-0074847-1: FCC_disclaimer; Library Reference: Logo
Logo4 = CMP-0074769-1
ZZ1 = CMP-0003616-3
ZZ2 = CMP-0077236-1
ZZ3 = CMP-0077237-1
ZZ4 = CMP-0077238-1

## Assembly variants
001: not fitted FID1 FID2 FID3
